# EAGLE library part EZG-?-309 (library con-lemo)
LEMO Connector Source: http://www.lemo.com/pdfs/catalog/ROW/German/unipole_multipole.pdf
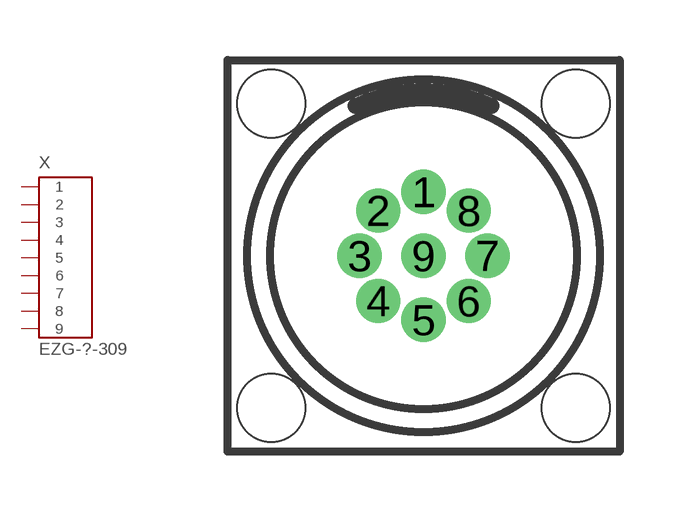
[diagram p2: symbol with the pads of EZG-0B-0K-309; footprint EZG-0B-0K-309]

Designator prefix X

## EZG-0B-309 (OC_FARNELL: unknown; OC_NEWARK: unknown)  [EZG-0B-0K-309]
1  1  pas
2  2  pas
3  3  pas
4  4  pas
5  5  pas
6  6  pas
7  7  pas
8  8  pas
9  9  pas

## EZG-0K-309 (OC_FARNELL: unknown; OC_NEWARK: unknown)  [EZG-0B-0K-309]
Pads as for EZG-0B-0K-309

## Footprint EZG-0B-0K-309 (pad centres in mm)
LEMO Connector Source: http://www.lemo.com/pdfs/catalog/ROW/German/unipole_multipole.pdf
drill 0.6 pad 1 round: 1 0,1.6; 2 -1.131,1.131; 3 -1.6,0; 4 -1.131,-1.131; 5 0,-1.6; 6 1.131,-1.131; 7 1.6,0; 8 1.131,1.131; 9 0,0
hole 1.7 at -3.81,3.81
hole 1.7 at 3.81,3.81
hole 1.7 at 3.81,-3.81
hole 1.7 at -3.81,-3.81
